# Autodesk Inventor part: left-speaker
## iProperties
Author: Administrator
Created: 2001-03
Part Number: left-speaker
Document SubType Name: Modeling
Designer: Administrator
Control State: 0
Master: False
Checked Out: False
PropertySet Name: Design Tracking Control
Shininess: 0.0
PropertySet Name: _Private Model Information
Density: 0.0
Volumn: 0.0
Area: 0.0
PropertySet Name: Model Information
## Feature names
1. Derived Body1 [Tagging]
